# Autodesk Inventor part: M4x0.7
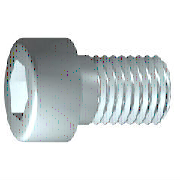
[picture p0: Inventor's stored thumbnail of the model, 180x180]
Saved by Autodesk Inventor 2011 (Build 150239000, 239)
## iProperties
IsCustomPart: 1
Created: 2009-02
Part Number: M4x0.7
Material: 강, 연강
Description: 6각머리 태핑 나사
Document SubType Name: Modeling
Standard: KS B 1003
Designer: SeoGD™[esajin.kr]
Standards Organization: KS
Language: ko-KR
Size Designation: M 4 x 16
Categories: <MemberInstance><Categories><Category DisplayName="조임쇠" InternalName="e4da775c-781d-43d5-af7c-5136215cf5a6" Mnemonic="FSTN"><Category DisplayName="볼트" InternalN
Density: 7.86 g/cm^3
Mass: 2.62973 g
Surface Area: 3.81119 cm^2
Volume: 0.334572 cm^3
Author: SeoGD™[esajin.kr]
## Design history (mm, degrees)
body "Solid1"
workplane "Work Plane1"
fillet "Fillet2" dims "d30" = 0.1 (= R)
revolve "본체" stored, may be unused: angle "d10" = 90 deg
sketch "스케치2"
  geometry: L1 (0, -4.9)-(0, 4.9) reference; L2 (-4.9, 0)-(4.9, 0) reference; L3 (1.732, 0)-(0.866, -1.5); L4 (0.866, -1.5)-(-0.866, -1.5); L5 (-0.866, -1.5)-(-1.732, 0); L6 (-1.732, 0)-(-0.866, 1.5); L7 (-0.866, 1.5)-(0.866, 1.5); L8 (0.866, 1.5)-(1.732, 0); 2 further points
  constraints: 12 end point, 1 coincident, 1 horizontal alignment, 1 point on line, 12 other
extrude "슬롯" join sketch "스케치2" stored distance "d11" = 10; taper "d12" = 0 deg
fillet "모깎기1" dims "d17" = 0.4 (= RR)
feature "스레드" dims "d13" = 14.25 (= GEL), "d14" = 0
chamfer "모따기1" distance "d15" = 0.42941 (= -0.5 x SPD + 0.5 x GD); stored, may be unused: second distance "d16" = 0.42941 (= GUL), angle "d27" = 45 deg
sketch "스케치1"
  geometry: L1 (-1, 0)-(16, 0); L2 (16, 0)-(16, 2); L3 (16, 2)-(1.75, 2); L4 (1.75, 2)-(1.32, 2); L5 (1.32, 2)-(0, 2); L6 (0, 2)-(0, 3.5); L7 (0, 3.5)-(-4, 3.5); L8 (-4, 3.5)-(-4, 1.732); L9 (-4, 1.732)-(-2, 1.732); L10 (-2, 1.732)-(-1, 0); L11 (-8, 0)-(20, 0) reference; L12 (0, -0.7)-(0, 4.2) reference; L13 (1.75, 2)-(0, 2)
  constraints: 22 end point, 6 parallel, 2 collinear, 2 perpendicular, 1 horizontal, 1 point on line
  dimensions: "d1" = 14.25 distance from line of L3.end L2 (= GEL); "d2" = 0.42952 distance of L4.end L3.end (computed from GAL); "d3" = 4 distance between parallel lines of L8 L6 (= KOH); "d4" = 2 distance of L8.end L9.end (= INTI); "d5" = 60 deg angle of L10 L1; "d6" = 4 diameter of L3 L1 (= GD); "d7" = 4 diameter of L5 L1 (= BDM); "d8" = 3.4641 diameter of L9 L1 (= 1.1547 x SW); "d9" = 7 diameter of L7 L1 (= KOD); "d26" = 16 distance between parallel lines of L12 L2 (= NLG)
other parameters: "GD" = 4 (= NND) [user parameter; used in 2 equation terms], "NLG" = 16 [user parameter; used in 1 equation term], "GEL" = 14.25 [user parameter; used in 2 equation terms], "KOD" = 7 [user parameter; used in 1 equation term], "KOH" = 4 [user parameter; used in 1 equation term], "INTI" = 2 [user parameter; used in 1 equation term], "GAL" = 0.42941 (= 0.61345 x PTC) [user parameter; used in 1 equation term], "GUL" = 0.42941 (= 0.61345 x PTC) [user parameter; used in 1 equation term], "BDM" = 4 (= NND) [user parameter; used in 1 equation term], "SW" = 3 [user parameter; used in 2 equation terms], "RR" = 0.4 [user parameter; used in 1 equation term], "SPD" = 3.14117 (= NND - 1.2269 x PTC) [user parameter; used in 1 equation term], "d19" = 0, "d28" = 0, "d29" = 0, "R" = 0.1 [user parameter; used in 1 equation term], "PHH" = 0.2 [user parameter], "GD1" = 3.14117 (= THREADDIA - 1.2269 x PTC) [user parameter], "THREADDIA" = 4 [user parameter; used in 1 equation term], "FAWI" = 45 deg [user parameter], "TPU" = 14.28571 (computed from PTC) [user parameter], "PTC" = 0.7 [user parameter; used in 5 equation terms], "NND" = 4 [user parameter; used in 3 equation terms], "TOA" = 30 deg [user parameter], "E0" = 3.465 (= 1.155 x SW) [user parameter]
